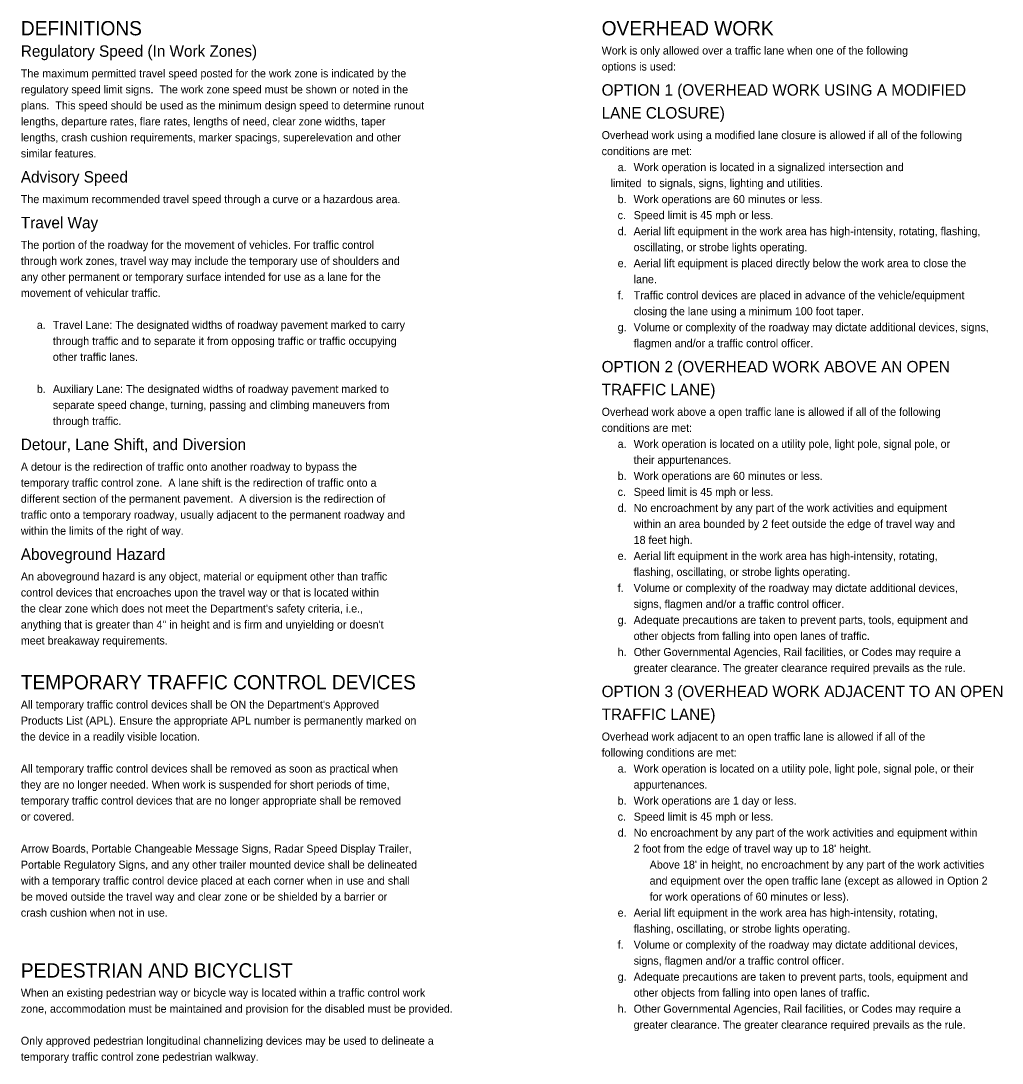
# Model space of a CAD drawing. Extents: x 10000 to 10773, y 9585 to 10515.
# Drawn here: x 10044 to 10473.2, y 10059.1 to 10514.8 of the extents above; entities that cross this region are included whole.
import ezdxf

# ---------------------------------------------------------------- set-up
doc = ezdxf.new("R2010")
doc.units = 0
doc.layers.add('SupstrConc', color=7, linetype='Continuous')

msp = doc.modelspace()

# ---------------------------------------------------------------- texts
at = {"layer": 'SupstrConc'}
for s, height, p in [('DEFINITIONS', 6.25, (10044.03, 10508.5)), ('OVERHEAD WORK', 6.25, (10298.06, 10508.5)), ('Regulatory Speed (In Work Zones)', 5, (10044.03, 10499.12)), ('Work is only allowed over a traffic lane when one of the following ', 3.5, (10298.06, 10500.12)), ('options is used:', 3.5, (10298.06, 10493.12)), ('The maximum permitted travel speed posted for the work zone is indicated by the ', 3.5, (10044.03, 10490.12)), ('OPTION 1 (OVERHEAD WORK USING A MODIFIED ', 5, (10298.06, 10482.12)), ('regulatory speed limit signs.  The work zone speed must be shown or noted in the ', 3.5, (10044.03, 10483.12)), ('plans.  This speed should be used as the minimum design speed to determine runout ', 3.5, (10044.03, 10476.12)), ('LANE CLOSURE)', 5, (10298.06, 10472.12)), ('lengths, departure rates, flare rates, lengths of need, clear zone widths, taper ', 3.5, (10044.03, 10469.12)), ('lengths, crash cushion requirements, marker spacings, superelevation and other ', 3.5, (10044.03, 10462.12)), ('Overhead work using a modified lane closure is allowed if all of the following ', 3.5, (10298.06, 10463.12)), ('similar features.  ', 3.5, (10044.03, 10455.12)), ('conditions are met:', 3.5, (10298.06, 10456.12)), ('a.', 3.5, (10305.06, 10449.12)), ('Work operation is located in a signalized intersection and ', 3.5, (10312.06, 10449.12)), ('Advisory Speed', 5, (10044.03, 10444.12)), ('   limited  to signals, signs, lighting and utilities.', 3.5, (10298.06, 10442.12)), ('The maximum recommended travel speed through a curve or a hazardous area. ', 3.5, (10044.03, 10435.12)), ('b.', 3.5, (10305.06, 10435.12)), ('Work operations are 60 minutes or less.', 3.5, (10312.06, 10435.12)), ('Travel Way', 5, (10044.03, 10424.12)), ('c.', 3.5, (10305.06, 10428.12)), ('Speed limit is 45 mph or less.', 3.5, (10312.06, 10428.12)), ('d.', 3.5, (10305.06, 10421.12)), ('Aerial lift equipment in the work area has high-intensity, rotating, flashing, ', 3.5, (10312.06, 10421.12)), ('The portion of the roadway for the movement of vehicles. For traffic control ', 3.5, (10044.03, 10415.12)), ('oscillating, or strobe lights operating.', 3.5, (10312.06, 10414.12)), ('through work zones, travel way may include the temporary use of shoulders and ', 3.5, (10044.03, 10408.12)), ('Aerial lift equipment is placed directly below the work area to close the ', 3.5, (10312.06, 10407.12)), ('e.', 3.5, (10305.06, 10407.12)), ('any other permanent or temporary surface intended for use as a lane for the ', 3.5, (10044.03, 10401.12)), ('lane.', 3.5, (10312.06, 10400.12)), ('movement of vehicular traffic.', 3.5, (10044.03, 10394.12)), ('f.', 3.5, (10305.06, 10393.12)), ('Traffic control devices are placed in advance of the vehicle/equipment ', 3.5, (10312.06, 10393.12)), ('closing the lane using a minimum 100 foot taper.', 3.5, (10312.06, 10386.12)), ('a.', 3.5, (10051.03, 10380.12)), ('Travel Lane: The designated widths of roadway pavement marked to carry ', 3.5, (10058.03, 10380.12)), ('Volume or complexity of the roadway may dictate additional devices, signs, ', 3.5, (10312.06, 10379.12)), ('g.', 3.5, (10305.06, 10379.12)), ('through traffic and to separate it from opposing traffic or traffic occupying ', 3.5, (10058.03, 10373.12)), ('flagmen and/or a traffic control officer.', 3.5, (10312.06, 10372.12)), ('other traffic lanes.', 3.5, (10058.03, 10366.12)), ('OPTION 2 (OVERHEAD WORK ABOVE AN OPEN ', 5, (10298.06, 10361.12)), ('b.', 3.5, (10051.03, 10352.12)), ('Auxiliary Lane: The designated widths of roadway pavement marked to ', 3.5, (10058.03, 10352.12)), ('TRAFFIC LANE)', 5, (10298.06, 10351.12)), ('separate speed change, turning, passing and climbing maneuvers from ', 3.5, (10058.03, 10345.12)), ('through traffic.', 3.5, (10058.03, 10338.12)), ('Overhead work above a open traffic lane is allowed if all of the following ', 3.5, (10298.06, 10342.12)), ('conditions are met: ', 3.5, (10298.06, 10335.12)), ('Detour, Lane Shift, and Diversion', 5, (10044.03, 10327.12)), ('a.', 3.5, (10305.06, 10328.12)), ('Work operation is located on a utility pole, light pole, signal pole, or ', 3.5, (10312.06, 10328.12)), ('their appurtenances.', 3.5, (10312.06, 10321.12)), ('A detour is the redirection of traffic onto another roadway to bypass the ', 3.5, (10044.03, 10318.12)), ('temporary traffic control zone.  A lane shift is the redirection of traffic onto a ', 3.5, (10044.03, 10311.12)), ('b.', 3.5, (10305.06, 10314.12)), ('Work operations are 60 minutes or less.', 3.5, (10312.06, 10314.12)), ('c.', 3.5, (10305.06, 10307.12)), ('Speed limit is 45 mph or less.', 3.5, (10312.06, 10307.12)), ('different section of the permanent pavement.  A diversion is the redirection of ', 3.5, (10044.03, 10304.12)), ('traffic onto a temporary roadway, usually adjacent to the permanent roadway and ', 3.5, (10044.03, 10297.12)), ('d.', 3.5, (10305.06, 10300.12)), ('No encroachment by any part of the work activities and equipment ', 3.5, (10312.06, 10300.12)), ('within an area bounded by 2 feet outside the edge of travel way and ', 3.5, (10312.06, 10293.12)), ('within the limits of the right of way. ', 3.5, (10044.03, 10290.12)), ('18 feet high.', 3.5, (10312.06, 10286.12)), ('Aboveground Hazard ', 5, (10044.03, 10279.12)), ('Aerial lift equipment in the work area has high-intensity, rotating, ', 3.5, (10312.06, 10279.12)), ('e.', 3.5, (10305.06, 10279.12)), ('An aboveground hazard is any object, material or equipment other than traffic ', 3.5, (10044.03, 10270.12)), ('flashing, oscillating, or strobe lights operating.', 3.5, (10312.06, 10272.12)), ('f.', 3.5, (10305.06, 10265.12)), ('Volume or complexity of the roadway may dictate additional devices, ', 3.5, (10312.06, 10265.12)), ('control devices that encroaches upon the travel way or that is located within ', 3.5, (10044.03, 10263.12)), ("the clear zone which does not meet the Department's safety criteria, i.e., ", 3.5, (10044.03, 10256.12)), ('signs, flagmen and/or a traffic control officer.', 3.5, (10312.06, 10258.12)), ('anything that is greater than 4" in height and is firm and unyielding or doesn\'t ', 3.5, (10044.03, 10249.12)), ('g.', 3.5, (10305.06, 10251.12)), ('Adequate precautions are taken to prevent parts, tools, equipment and ', 3.5, (10312.06, 10251.12)), ('meet breakaway requirements. ', 3.5, (10044.03, 10242.12)), ('other objects from falling into open lanes of traffic.', 3.5, (10312.06, 10244.12)), ('h.', 3.5, (10305.06, 10237.12)), ('Other Governmental Agencies, Rail facilities, or Codes may require a ', 3.5, (10312.06, 10237.12)), ('greater clearance. The greater clearance required prevails as the rule.', 3.5, (10312.06, 10230.12)), ('TEMPORARY TRAFFIC CONTROL DEVICES', 6.25, (10044.03, 10222.5)), ('OPTION 3 (OVERHEAD WORK ADJACENT TO AN OPEN ', 5, (10298.06, 10219.12)), ("All temporary traffic control devices shall be ON the Department's Approved ", 3.5, (10044.03, 10214.12)), ('TRAFFIC LANE)', 5, (10298.06, 10209.12)), ('Products List (APL). Ensure the appropriate APL number is permanently marked on ', 3.5, (10044.03, 10207.12)), ('the device in a readily visible location.', 3.5, (10044.03, 10200.12)), ('Overhead work adjacent to an open traffic lane is allowed if all of the ', 3.5, (10298.06, 10200.12)), ('following conditions are met: ', 3.5, (10298.06, 10193.12)), ('All temporary traffic control devices shall be removed as soon as practical when ', 3.5, (10044.03, 10186.12)), ('a.', 3.5, (10305.06, 10186.12)), ('Work operation is located on a utility pole, light pole, signal pole, or their ', 3.5, (10312.06, 10186.12)), ('they are no longer needed. When work is suspended for short periods of time, ', 3.5, (10044.03, 10179.12)), ('appurtenances.', 3.5, (10312.06, 10179.12)), ('temporary traffic control devices that are no longer appropriate shall be removed ', 3.5, (10044.03, 10172.12)), ('b.', 3.5, (10305.06, 10172.12)), ('Work operations are 1 day or less.', 3.5, (10312.06, 10172.12)), ('or covered.', 3.5, (10044.03, 10165.12)), ('Speed limit is 45 mph or less.', 3.5, (10312.06, 10165.12)), ('c.', 3.5, (10305.06, 10165.12)), ('d.', 3.5, (10305.06, 10158.12)), ('No encroachment by any part of the work activities and equipment within ', 3.5, (10312.06, 10158.12)), ('Arrow Boards, Portable Changeable Message Signs, Radar Speed Display Trailer, ', 3.5, (10044.03, 10151.12)), ("2 foot from the edge of travel way up to 18' height.", 3.5, (10312.06, 10151.12)), ('Portable Regulatory Signs, and any other trailer mounted device shall be delineated ', 3.5, (10044.03, 10144.12)), ("Above 18' in height, no encroachment by any part of the work activities ", 3.5, (10319.06, 10144.12)), ('with a temporary traffic control device placed at each corner when in use and shall ', 3.5, (10044.03, 10137.12)), ('and equipment over the open traffic lane (except as allowed in Option 2 ', 3.5, (10319.06, 10137.12)), ('be moved outside the travel way and clear zone or be shielded by a barrier or ', 3.5, (10044.03, 10130.12)), ('for work operations of 60 minutes or less).', 3.5, (10319.06, 10130.12)), ('crash cushion when not in use.', 3.5, (10044.03, 10123.12)), ('e.', 3.5, (10305.06, 10123.12)), ('Aerial lift equipment in the work area has high-intensity, rotating, ', 3.5, (10312.06, 10123.12)), ('flashing, oscillating, or strobe lights operating.', 3.5, (10312.06, 10116.12)), ('f.', 3.5, (10305.06, 10109.12)), ('Volume or complexity of the roadway may dictate additional devices, ', 3.5, (10312.06, 10109.12)), ('signs, flagmen and/or a traffic control officer.', 3.5, (10312.06, 10102.12)), ('PEDESTRIAN AND BICYCLIST', 6.25, (10044.03, 10096.5)), ('g.', 3.5, (10305.06, 10095.12)), ('Adequate precautions are taken to prevent parts, tools, equipment and ', 3.5, (10312.06, 10095.12)), ('When an existing pedestrian way or bicycle way is located within a traffic control work ', 3.5, (10044.03, 10088.12)), ('other objects from falling into open lanes of traffic.', 3.5, (10312.06, 10088.12)), ('zone, accommodation must be maintained and provision for the disabled must be provided.', 3.5, (10044.03, 10081.12)), ('h.', 3.5, (10305.06, 10081.12)), ('Other Governmental Agencies, Rail facilities, or Codes may require a ', 3.5, (10312.06, 10081.12)), ('greater clearance. The greater clearance required prevails as the rule.', 3.5, (10312.06, 10074.12)), ('Only approved pedestrian longitudinal channelizing devices may be used to delineate a ', 3.5, (10044.03, 10067.12)), ('temporary traffic control zone pedestrian walkway.', 3.5, (10044.03, 10060.12))]:
    msp.add_text(s, height=height, dxfattribs=at).set_placement(p)

doc.saveas('drawing.dxf')
